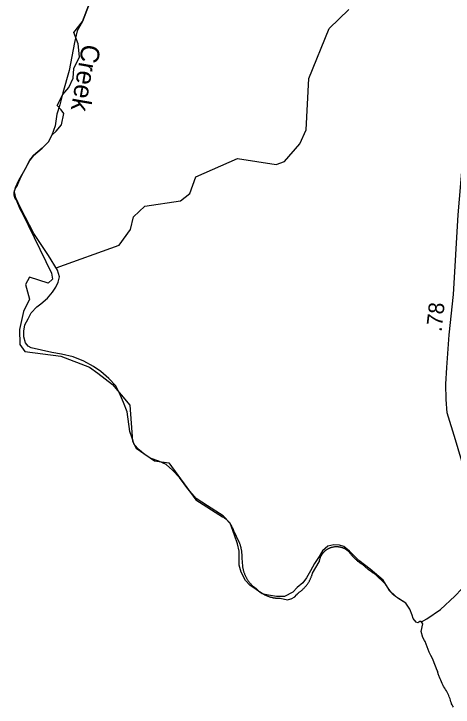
# Model space of a CAD drawing. Extents: x 2220236 to 2384410, y 720751 to 894131.
# Drawn here: x 2232732 to 2236238, y 720823 to 726359 of the extents above; entities that cross this region are included whole.
import ezdxf

# ---------------------------------------------------------------- set-up
doc = ezdxf.new("R2010")
doc.units = 0
for name, color, linetype in [('Exist Boundary Political CountyLine', 7, 'Continuous'), ('Exist Hydrographic Creek Single Shore', 7, 'Continuous'), ('Exist Hydrographic Creek Single Shore Label', 7, 'Continuous'), ('Exist Hydrographic Misc Water Feature', 7, 'Continuous'), ('Exist Road Primary NC Attributed', 7, 'Continuous'), ('Exist Road Primary NC Service Mileage Hundredths English Label', 7, 'Continuous')]:
    doc.layers.add(name, color=color, linetype=linetype)

msp = doc.modelspace()

# ---------------------------------------------------------------- linework, layer by layer
at = {"layer": 'Exist Boundary Political CountyLine'}
for points in [[(2232859.2, 725191.3), (2232889.7, 725227.4), (2232959.1, 725285.8), (2233009.1, 725338.5), (2233034, 725391.3), (2233070.2, 725422.5), (2233110.9, 725474), (2233130.2, 725564.1), (2233108.8, 725594.1), (2233078.8, 725626.3), (2233121.7, 725716.4), (2233171, 725772.2), (2233205.3, 725845.2), (2233211.8, 725922.4), (2233254.7, 726016.8), (2233244, 726119.8), (2233211.8, 726210), (2233279.7, 726299.5), (2233326.9, 726424.5)], [(2232859.2, 725191.3), (2232788.9, 725058.6), (2232760.1, 724997.5), (2232755.3, 724980.6), (2232753.5, 724978.7), (2232751.9, 724976.8), (2232750.2, 724974.8), (2232748.8, 724972.8), (2232747.3, 724970.8), (2232745.7, 724968.6), (2232744.3, 724966.5), (2232743, 724964.3), (2232741.8, 724962.1), (2232740.6, 724959.7), (2232739.5, 724957.5), (2232738.5, 724955.1), (2232737.5, 724952.8), (2232736.7, 724950.4), (2232736.1, 724948), (2232735.2, 724945.5), (2232734.4, 724943), (2232734, 724940.6), (2232733.6, 724938), (2232733, 724935.5), (2232732.8, 724933), (2232732.6, 724930.4), (2232732.2, 724927.9), (2232732.2, 724925.3), (2232732.2, 724922.8), (2232732.2, 724920.3), (2232732.2, 724917.7), (2232732.6, 724915.1), (2232732.8, 724912.6), (2232733.2, 724910.1), (2232733.8, 724907.6), (2232734.2, 724905), (2232734.8, 724902.6), (2232735.4, 724900.1), (2232736.3, 724897.7), (2232737.3, 724895.3), (2232737.9, 724892.9), (2232738.9, 724890.5), (2232740.2, 724888.2), (2232741.2, 724885.9), (2232742.4, 724883.7), (2232743.6, 724881.5), (2232745.1, 724879.3), (2232746.5, 724877.2), (2232748, 724875.1), (2232749.6, 724873.1), (2232780.8, 724801.6), (2232783.4, 724796.6), (2232801.1, 724764.4), (2233032.8, 724288.2), (2233039.5, 724241.1), (2233006.5, 724208.1), (2232855.8, 724257), (2232823.8, 724196.8), (2232857, 724081.8), (2232810.1, 723983.1), (2232777.5, 723838.4), (2232780.6, 723718.1), (2232819.5, 723662.2), (2233105.8, 723624.4), (2233335.8, 723537.8), (2233401.3, 723489.3), (2233519.6, 723400.4), (2233658.2, 723233.1), (2233678.1, 722948.1), (2233708.4, 722890.3), (2233853.8, 722790.5), (2233969.4, 722773.7), (2234185.2, 722479), (2234397.8, 722343.6), (2234401.1, 722341.6), (2234404.2, 722339.4), (2234407.4, 722337.2), (2234410.7, 722335), (2234414, 722332.7), (2234417.3, 722330.3), (2234420.2, 722328), (2234423.2, 722325.4), (2234426.3, 722322.9)], [(2234426.3, 722322.9), (2234429.2, 722320.3), (2234432, 722317.5), (2234434.9, 722314.9), (2234437.8, 722312.1), (2234440.5, 722309.2), (2234442.9, 722306.4), (2234445.8, 722303.4), (2234448.2, 722300.4), (2234450.7, 722297.4), (2234453.2, 722294.3), (2234455.4, 722291.2), (2234457.7, 722288), (2234459.9, 722284.7), (2234462.2, 722281.5), (2234464.2, 722278.1), (2234466.3, 722274.8), (2234468.3, 722271.4), (2234470.2, 722267.9), (2234472, 722264.5), (2234473.7, 722261), (2234475.5, 722257.4), (2234477.2, 722253.9), (2234478.8, 722250.2), (2234480.2, 722246.6), (2234481.7, 722243), (2234482.9, 722239.3), (2234484.3, 722235.5), (2234485.6, 722231.8), (2234486.6, 722228), (2234528, 722143.8), (2234530.1, 722138.9), (2234531.7, 722134), (2234533.5, 722129.1), (2234535.2, 722124.2), (2234536.8, 722119.3), (2234538.3, 722114.3), (2234539.7, 722109.3), (2234540.9, 722104.3), (2234542.2, 722099.3), (2234543.6, 722094.2), (2234544.4, 722089.1), (2234545.4, 722084), (2234546.5, 722078.9), (2234547.5, 722073.8), (2234548.3, 722068.7), (2234548.9, 722063.5), (2234549.5, 722058.4), (2234550, 722053.2), (2234550.6, 722048.1), (2234551, 722042.9), (2234551.2, 722037.7), (2234551.6, 722032.5), (2234551.6, 722027.3), (2234551.6, 722022.1), (2234551.6, 722016.9), (2234551.6, 722011.8), (2234552.4, 722001.3), (2234553.2, 721990.9), (2234554.3, 721980.4), (2234555.1, 721969.9), (2234555.7, 721959.4), (2234556.5, 721948.9), (2234557.3, 721944.3), (2234557.9, 721939.7), (2234558.8, 721935.2), (2234559.8, 721930.6), (2234560.8, 721926), (2234562, 721921.5), (2234563.1, 721917), (2234564.3, 721912.5), (2234565.7, 721908), (2234567, 721903.5), (2234568.4, 721899.1), (2234570, 721894.7), (2234571.7, 721890.4), (2234573.5, 721886), (2234575.2, 721881.7), (2234577, 721877.5), (2234579.1, 721873.2), (2234580.9, 721868.9), (2234583, 721864.7), (2234585.2, 721860.6), (2234587.3, 721856.5), (2234589.5, 721852.4), (2234592, 721848.4), (2234594.2, 721844.4), (2234596.7, 721840.4), (2234599.2, 721836.5), (2234602, 721832.6), (2234604.5, 721828.8)], [(2235028.3, 721755.2), (2235031.8, 721758.3), (2235035.3, 721761.3), (2235038.6, 721764.4), (2235042.1, 721767.6), (2235045.2, 721770.9), (2235048.4, 721774.2), (2235051.7, 721777.5), (2235054.8, 721780.9), (2235058.1, 721784.4), (2235060.9, 721787.9), (2235064, 721791.5), (2235066.7, 721795.1), (2235069.8, 721798.8), (2235072.4, 721802.5), (2235075.1, 721806.2), (2235077.8, 721810), (2235080.2, 721813.9), (2235082.7, 721817.8), (2235085.3, 721821.7), (2235087.8, 721825.7), (2235090.1, 721829.7), (2235092.3, 721833.8), (2235094.2, 721837.9), (2235096.4, 721842.1), (2235098.5, 721846.2), (2235100.5, 721850.4), (2235102.2, 721854.6), (2235104, 721858.9), (2235105.8, 721863.2), (2235107.5, 721867.6), (2235108.9, 721871.9), (2235110.6, 721876.3), (2235112, 721880.7), (2235113.4, 721885.1), (2235114.7, 721889.6), (2235116.1, 721894.1), (2235169.4, 721983.1), (2235170, 721986.4), (2235170.4, 721989.6), (2235171.1, 721992.9), (2235171.7, 721996.2), (2235172.5, 721999.5), (2235173.3, 722002.7), (2235174.3, 722005.9), (2235175.2, 722009), (2235176.2, 722012.3), (2235177.4, 722015.3), (2235178.4, 722018.5), (2235179.7, 722021.6), (2235181.3, 722024.6), (2235182.7, 722027.6), (2235184.2, 722030.6), (2235185.8, 722033.5), (2235187.3, 722036.4), (2235189.1, 722039.3), (2235190.7, 722042.1), (2235192.8, 722044.9), (2235194.4, 722047.6), (2235196.5, 722050.3), (2235198.5, 722052.9), (2235200.8, 722055.5), (2235203, 722058.1), (2235205.1, 722060.5), (2235207.6, 722062.9), (2235209.8, 722065.3), (2235212.3, 722067.6), (2235214.5, 722069.9), (2235217, 722072), (2235219.7, 722074.3), (2235222.3, 722076.3), (2235225, 722078.3), (2235227.6, 722080.2), (2235230.5, 722082.1), (2235233.2, 722083.9), (2235236.1, 722085.7), (2235238.9, 722087.4), (2235241.8, 722088.9), (2235244.7, 722090.5), (2235247.7, 722091.9), (2235250.8, 722093.3), (2235254.1, 722094.7), (2235257, 722095.9), (2235260, 722097.1), (2235263.3, 722098.2), (2235266.4, 722099.2), (2235269.5, 722100.1), (2235272.8, 722101), (2235276, 722101.7), (2235279.3, 722102.4), (2235282.4, 722103.1), (2235286.1, 722103.6), (2235289.2, 722104.1), (2235292.4, 722104.5), (2235295.7, 722104.8), (2235299.2, 722105.1), (2235302.5, 722105.2), (2235305.8, 722105.3), (2235309.3, 722105.3), (2235312.5, 722105.1)], [(2235312.5, 722105.1), (2235315.8, 722105), (2235319.1, 722104.8), (2235322.6, 722104.4), (2235325.7, 722104), (2235328.9, 722103.5), (2235332.2, 722103), (2235335.5, 722102.3), (2235338.8, 722101.6), (2235342.1, 722100.8), (2235345.3, 722099.9), (2235348.4, 722098.9), (2235351.7, 722097.9), (2235354.8, 722096.8), (2235358.1, 722095.6), (2235360.9, 722094.3), (2235364, 722093), (2235367.1, 722091.6), (2235370, 722090), (2235373, 722088.5), (2235375.9, 722086.9), (2235378.8, 722085.2), (2235381.4, 722083.4), (2235384.5, 722081.6), (2235387.2, 722079.7), (2235389.8, 722077.7), (2235392.5, 722075.7), (2235395, 722073.6), (2235397.4, 722071.5), (2235400.1, 722069.2), (2235402.6, 722067), (2235405, 722064.7), (2235407.3, 722062.3), (2235410.6, 722057.8), (2235414, 722053.4), (2235417.3, 722049), (2235420.8, 722044.7), (2235424.3, 722040.4), (2235428, 722036.2), (2235431.5, 722032), (2235435.2, 722028), (2235439.1, 722023.8), (2235443, 722019.8), (2235446.8, 722015.9), (2235450.7, 722012), (2235454.8, 722008.1), (2235458.7, 722004.4), (2235463, 722000.6), (2235466.9, 721996.9), (2235471.3, 721993.4), (2235475.6, 721989.8), (2235480.1, 721986.3), (2235484.2, 721982.9), (2235488.7, 721979.6), (2235493.2, 721976.2), (2235497.7, 721973), (2235502.2, 721969.8), (2235506.7, 721966.8), (2235511.4, 721963.7), (2235516.2, 721960.8), (2235520.7, 721957.8), (2235526, 721953.1), (2235531.3, 721948.3), (2235536.5, 721943.6), (2235541.8, 721939), (2235547.3, 721934.5), (2235552.5, 721930), (2235558, 721925.5), (2235563.5, 721921.2), (2235569.3, 721916.9), (2235574.8, 721912.7), (2235580.5, 721908.5), (2235586.3, 721904.4), (2235592, 721900.4), (2235597.8, 721896.4), (2235603.7, 721892.5), (2235609.5, 721888.7), (2235615.4, 721884.9), (2235642.1, 721858.9), (2235668.3, 721832.9), (2235694.8, 721806.8), (2235698.7, 721800.8), (2235702.8, 721794.8), (2235706.7, 721788.7), (2235710.8, 721782.6), (2235714.4, 721776.4), (2235718.3, 721770.2), (2235722, 721764), (2235725.7, 721757.7), (2235730.4, 721752.1), (2235735.6, 721746.4), (2235740.5, 721740.7), (2235745.2, 721735), (2235749.9, 721729.3), (2235750.4, 721728.6)], [(2234604.5, 721828.8), (2234607.2, 721825), (2234610, 721821.3), (2234612.9, 721817.6), (2234616, 721813.9), (2234618.8, 721810.4), (2234621.9, 721806.8), (2234625, 721803.3), (2234628.3, 721799.9), (2234631.2, 721796.5), (2234634.8, 721793.2), (2234640.2, 721789.1), (2234645.7, 721785.1), (2234651.2, 721780.9), (2234656.8, 721776.6), (2234661.9, 721772.4), (2234667.2, 721768), (2234672.8, 721763.6), (2234677.7, 721759.1), (2234683, 721754.6), (2234688.2, 721750), (2234693.3, 721745.3), (2234697, 721742.6), (2234700.7, 721739.9), (2234704.6, 721737.3), (2234708.5, 721734.8), (2234712.6, 721732.3), (2234716.2, 721729.9), (2234720.4, 721727.6), (2234724.5, 721725.3), (2234728.6, 721723.2), (2234732.4, 721721), (2234736.8, 721718.9), (2234741.1, 721716.9), (2234745.2, 721715.1), (2234749.5, 721713.2), (2234753.8, 721711.5), (2234758.1, 721709.8), (2234762.2, 721708.1), (2234766.7, 721706.6), (2234771, 721705.1), (2234775.5, 721703.8), (2234780, 721702.4), (2234784.5, 721701.2), (2234789, 721700), (2234793.6, 721699), (2234798.1, 721697.9), (2234802.6, 721697), (2234807.1, 721696.1), (2234811.6, 721695.4), (2234816.3, 721694.7), (2234820.8, 721694.1), (2234825.5, 721693.5), (2234830.1, 721693.1), (2234834.8, 721692.7), (2234839.3, 721692.4), (2234844, 721692.2), (2234848.5, 721692), (2234853.2, 721691.9), (2234857.7, 721692), (2234916, 721680), (2234941.8, 721686.8), (2234946.3, 721687.9), (2234973.4, 721704), (2234988.7, 721719.9), (2234992.6, 721722.2), (2234994.3, 721731), (2235002.3, 721735.9), (2235006, 721738.5), (2235009.7, 721741.1), (2235013.6, 721743.8), (2235017.3, 721746.6), (2235021, 721749.4), (2235024.4, 721752.3), (2235028.3, 721755.2)], [(2236241.8, 720822.9), (2236236.5, 720829.5), (2236234.7, 720831.8), (2236231.8, 720836.5), (2236228.7, 720841.4), (2236225.2, 720849), (2236223.8, 720854.8), (2236221.9, 720860.5), (2236220.5, 720866.2), (2236217, 720877.6), (2236212.9, 720888.8), (2236211.1, 720894.4), (2236206.8, 720905.5), (2236202.1, 720916.4), (2236196.9, 720927.2), (2236192, 720937.9), (2236189.3, 720943.2), (2236186.3, 720948.4), (2236183.6, 720953.6), (2236177.5, 720963.9), (2236174.6, 720969), (2236171.3, 720974), (2236164.7, 720983.9), (2236161.5, 720988.9), (2236158.2, 720994.8), (2236155.3, 721000.8), (2236149.2, 721012.8), (2236143.8, 721025), (2236138.3, 721037.4), (2236133.2, 721049.8), (2236128.4, 721062.4), (2236126.2, 721068.7), (2236123.9, 721075.1), (2236122.1, 721081.4), (2236115.9, 721100.7), (2236114.3, 721107.1), (2236111, 721115.9), (2236097.7, 721150.6), (2236087, 721176.4), (2236083.3, 721184.9), (2236071.8, 721210.3), (2236059.5, 721235.3), (2236050.7, 721251.8), (2236047.1, 721261.3), (2236014.5, 721346.2), (2236009.4, 721353.9), (2235995.4, 721378), (2235982.2, 721425.9), (2235994.6, 721488.4), (2235982, 721507.3), (2235971.8, 721505.7), (2235956.8, 721497), (2235943.9, 721502.7), (2235918.9, 721529.5), (2235910, 721558.1), (2235892.1, 721606.4), (2235860, 721652.8), (2235801, 721691.6), (2235778.1, 721707.6), (2235750.4, 721728.6)]]:
    msp.add_lwpolyline(points, dxfattribs=at)
at = {"layer": 'Exist Hydrographic Creek Single Shore'}
for points in [[(2233326.9, 726424.5), (2233279.7, 726299.5), (2233238.1, 726224.5), (2233215.8, 726130.1), (2233174.2, 725907.9), (2233122.9, 725727.4), (2233097.9, 725632.9), (2233075.7, 725558), (2233061.8, 725466.3), (2233034, 725391.3), (2233009.1, 725338.5), (2232959.1, 725285.8), (2232889.7, 725227.4), (2232859.2, 725191.3)], [(2235989.9, 721497), (2235982, 721507.3), (2235971.8, 721505.7), (2235956.8, 721497), (2235943.9, 721502.7), (2235918.9, 721529.5), (2235910, 721558.1), (2235892.1, 721606.4), (2235860, 721652.8), (2235797.4, 721693.9), (2235736.7, 721747.6), (2235712.7, 721780.6), (2235679.4, 721836.2), (2235576.7, 721925.1), (2235485.1, 721994.5), (2235410.1, 722069.5), (2235365.7, 722105.6), (2235329.6, 722116.7), (2235285.2, 722119.5), (2235238, 722108.4), (2235196.4, 722072.3), (2235168.6, 722025.1), (2235132.5, 721969.5), (2235099.2, 721911.2), (2235068.7, 721855.6), (2235038.2, 721816.8), (2234993.7, 721777.9), (2234957.7, 721741.8), (2234892.4, 721705.7), (2234828.6, 721705.7), (2234764.7, 721716.8), (2234714.8, 721727.9), (2234664.8, 721761.2), (2234617.6, 721794.5), (2234581.5, 721833.4), (2234545.5, 721900.1), (2234528.8, 721955.6), (2234528.8, 722011.2), (2234528.8, 722069.5), (2234517.7, 722127.8), (2234492.7, 722197.3), (2234459.4, 722291.7), (2234401.1, 722350), (2234276.2, 722430.6), (2234186, 722488.9), (2234119.4, 722566.7), (2234052.7, 722655.5), (2233997.2, 722716.6), (2233947.3, 722761.1), (2233889, 722786.1), (2233819.6, 722811.1), (2233772.4, 722844.4), (2233730.8, 722877.7), (2233691.9, 722919.4), (2233675.2, 722972.2), (2233657.2, 723024.9), (2233635, 723180.5), (2233607.2, 723255.5), (2233573.9, 723330.5), (2233546.2, 723388.8), (2233490.7, 723447.1), (2233426.8, 723502.7), (2233368.5, 723544.3), (2233290.8, 723586), (2233204.7, 723619.3), (2233113.1, 723641.5), (2233035.4, 723655.4), (2232870.3, 723691.5), (2232845.3, 723705.4), (2232825.9, 723733.2), (2232812, 723780.4), (2232812, 723824.8), (2232820.3, 723874.8), (2232845.3, 723924.8), (2232870.3, 723972), (2232914.7, 724019.3), (2232948, 724044.3), (2233000.7, 724088.7), (2233039.6, 724135.9), (2233067.3, 724177.6), (2233086.8, 724216.5), (2233096.5, 724258.1), (2233079.8, 724313.7), (2233007.7, 724430.3), (2232891.1, 724605.3), (2232788.4, 724805.3), (2232746.7, 724891.4), (2232738.4, 724938.6), (2232744, 724971.9), (2232771.7, 725030.2), (2232823.1, 725119.1), (2232859.2, 725191.3)]]:
    msp.add_lwpolyline(points, dxfattribs=at)
at = {"layer": 'Exist Hydrographic Misc Water Feature'}
msp.add_lwpolyline([(2233068.9, 724331.3), (2233572.2, 724512.2), (2233663.3, 724638.2), (2233687.3, 724739.4), (2233778.3, 724822.9), (2234061.3, 724866.3), (2234135.3, 724923.8), (2234184.3, 725057.3), (2234516.3, 725204.6), (2234825.3, 725155.6), (2234891.4, 725180.6), (2235015.2, 725322.3), (2235064.2, 725432.9), (2235086.4, 725842.4), (2235249.2, 726242.5), (2235406.3, 726393.5)], dxfattribs=at)
at = {"layer": 'Exist Road Primary NC Attributed'}
msp.add_lwpolyline([(2235984.8, 721503.1), (2236028.2, 721528.7), (2236136.5, 721602), (2236250.8, 721708.4), (2236306.4, 721768.9), (2236361.7, 721839.3), (2236409, 721927.5), (2236442.2, 722021.8), (2236451.6, 722099.8), (2236456.9, 722193.9), (2236425.5, 722367.4), (2236349.1, 722644.7), (2236257.5, 722956.3), (2236190.6, 723173), (2236182.2, 723279.2), (2236179.1, 723403), (2236186, 723535), (2236205.8, 723797.1), (2236241.3, 724117.1), (2236276.6, 724753.6), (2236311.7, 725161.5), (2236343.5, 725365.5)], dxfattribs=at)

# ---------------------------------------------------------------- texts
at = {"layer": 'Exist Hydrographic Creek Single Shore Label'}
msp.add_text('Creek', height=150, rotation=260.1114, dxfattribs=at).set_placement((2233278.2, 726123.7))
at = {"layer": 'Exist Road Primary NC Service Mileage Hundredths English Label'}
msp.add_text('.78', height=125, rotation=83.6619, dxfattribs=at).set_placement((2236145.1, 723816.9))

doc.saveas('drawing.dxf')
